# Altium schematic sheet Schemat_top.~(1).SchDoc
size A4; Author: Imię Nazwisko; CompanyName: AGH; Revision: 1
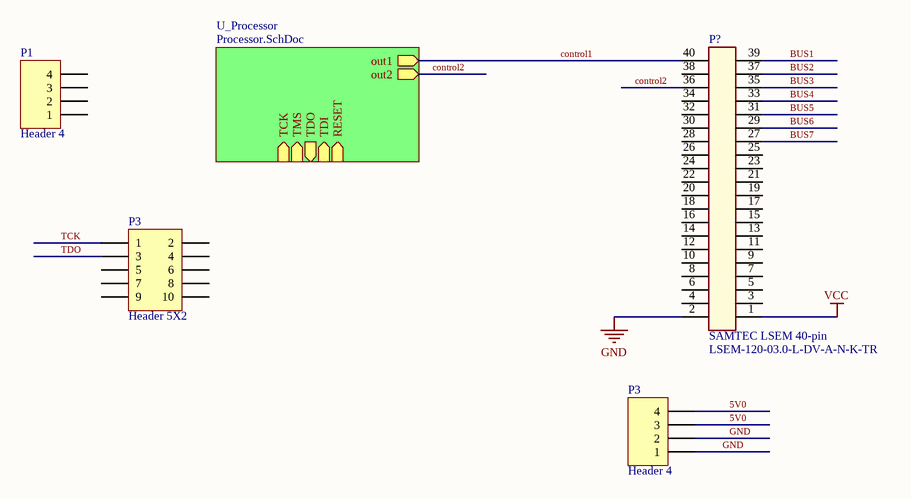
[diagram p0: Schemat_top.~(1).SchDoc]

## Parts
(Parts that share a designator on the sheet are numbered #1, #2 ... from top to bottom, then left to right.)
P1  Header 4  [HDR1X4]
P3#1  Header 5X2  [HDR2X5]
P3#2  Header 4  [HDR1X4]
P?  SAMTEC LSEM 40-pin  [LSEM-120-03.0-L-DV-A-N-K-TR]

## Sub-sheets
U_Processor = Processor.SchDoc: out1 (out), out2 (out), TCK (in), TMS (in), TDO (out), TDI (in), RESET (in)

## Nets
GND: P3#2.1 P3#2.2 P?.2
VCC: P?.1(PIN)
5V0: P3#2.3 P3#2.4
BUS1: P?.39(PIN)
BUS2: P?.37(PIN)
BUS3: P?.35(PIN)
BUS4: P?.33(PIN)
BUS5: P?.31(PIN)
BUS6: P?.29(PIN)
BUS7: P?.27(PIN)
control1: P?.40 ; sheet U_Processor/out1
control2: P?.36 ; sheet U_Processor/out2
TCK: P3#1.1
TDO: P3#1.3

Not connected (* = marked no-connect by the designer): P1 1 2 3 4; P3#1 2 4 5 6 7 8 9 10; P? 3(PIN) 4(3) 5(PIN) 6(4) 7(PIN) 8(5) 9(PIN) 10(6) 11(PIN) 12(7) 13(PIN) 14(8) 15(PIN) 16(9) 17(PIN) 18(10) 19(PIN) 20(11) 21(PIN) 22(12) 23(PIN) 24(13) 25(PIN) 26(14) 28(15) 30(16) 32(17) 34(18) 38(20)

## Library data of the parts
P1 P3#2 = Header 4: Header, 4-Pin
P3#1 = Header 5X2: Header, 5-Pin, Dual row
P? = SAMTEC LSEM 40-pin: Component desciption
